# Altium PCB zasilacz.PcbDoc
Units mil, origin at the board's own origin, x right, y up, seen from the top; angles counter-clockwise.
Board outline 7530 x 5310 mil, 2 copper layers (Top Layer, Bottom Layer); 78 components, 40 nets, 194 pads, 25 vias.
Unrouted connection lines stored in the file: 3.
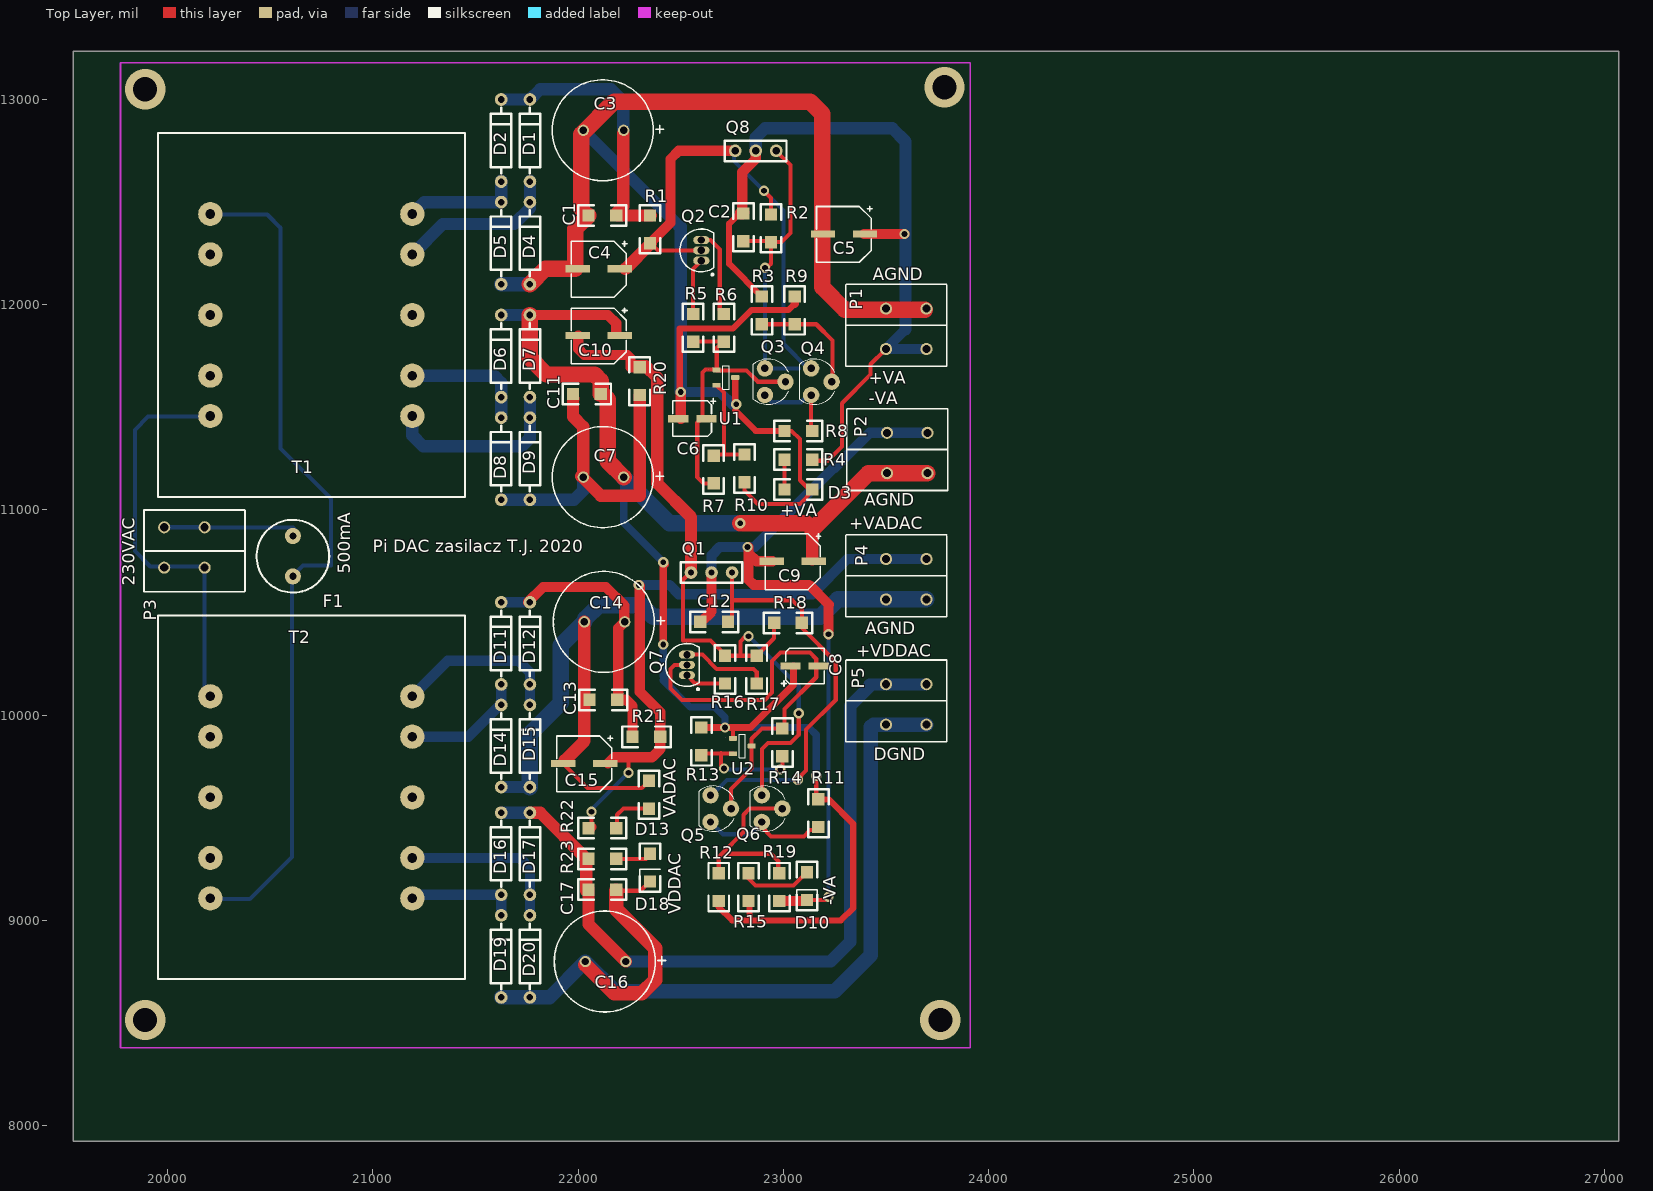
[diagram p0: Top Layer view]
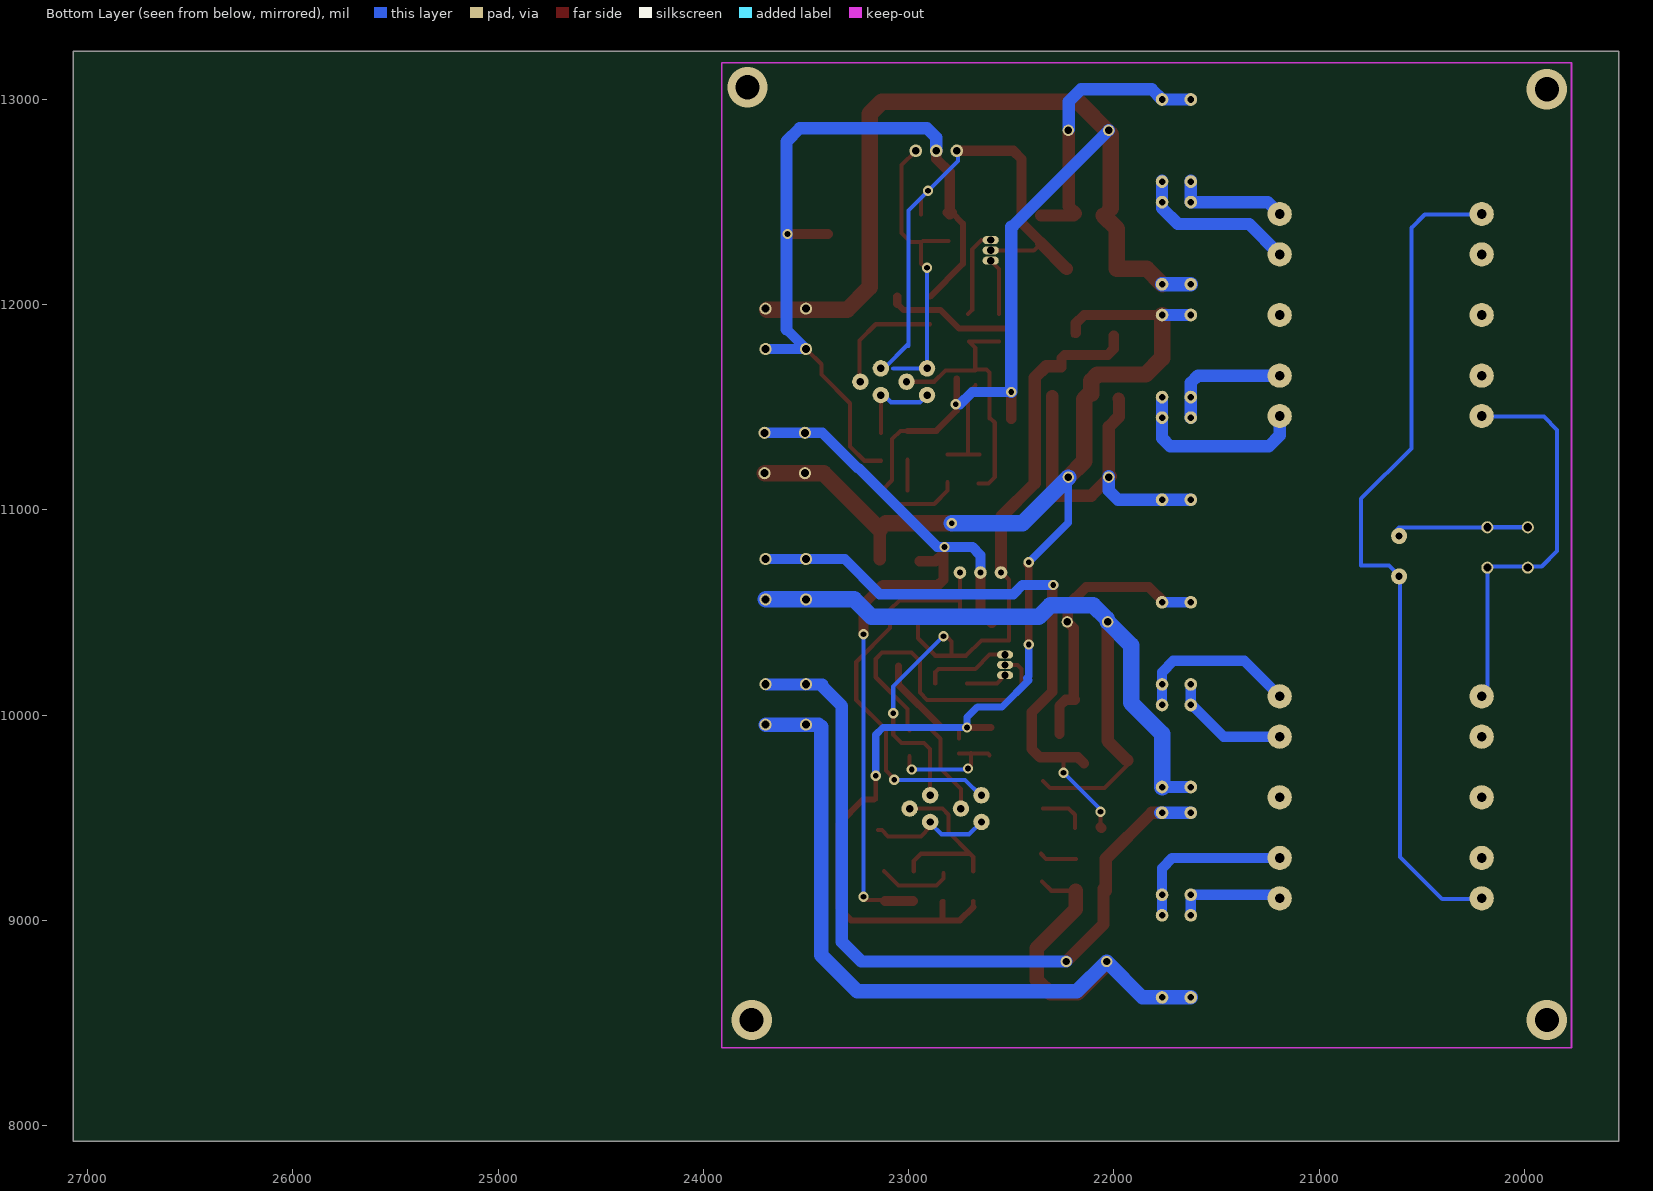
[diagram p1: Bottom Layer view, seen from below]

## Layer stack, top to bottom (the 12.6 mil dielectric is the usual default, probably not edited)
Top Solder: solder mask 0.4, Solder Resist, Dk 3.5
Top Layer: signal copper 1.4
Dielectric 1: dielectric 12.6, FR-4, Dk 4.8
Bottom Layer: signal copper 1.4
Bottom Solder: solder mask 0.4, Solder Resist, Dk 3.5

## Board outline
19540,7925 27070,7925 27070,13235 19540,13235

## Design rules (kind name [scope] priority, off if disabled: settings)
Clearance [All] p1: gap=10
PolygonConnect [All] p1: connectstyle=Relief reliefconductorwidth=10 reliefentries=4 polygonreliefangle="90 Angle" airgapwidth=10
RoomDefinition zasilacz [InComponentClass('zasilacz')] p1: confinementstyle=ConfineIn formatcopy=TRUE lockcomponents=FALSE outline 0,0 2000,0 2000,1000 0,1000
RoutingVias [All] p1: holewidth=28 width=50 viastyle="Through Hole" minholewidth=28 minwidth=50 maxholewidth=28 maxwidth=50
SolderMaskExpansion [All] p1: expansion=4
Width VA- [InNet('VA-')] p1: maxlimit=50 minlimit=50 preferedwidth=50
Width VA+ [InNet('VA+')] p2: maxlimit=50 minlimit=50 preferedwidth=50
Width VDDAC [InNet('+VDDAC')] p3: maxlimit=60 minlimit=60 preferedwidth=60
Width VADAC [InNet('+VADAC')] p4: maxlimit=50 minlimit=50 preferedwidth=50
Width board [All] p5: maxlimit=20 minlimit=20 preferedwidth=20
Width GND [InNet('GND')] p6: maxlimit=60 minlimit=60 preferedwidth=60
Width AGND [InNet('AGND')] p7: maxlimit=50 minlimit=50 preferedwidth=50
30 further rules are at their usual default settings.

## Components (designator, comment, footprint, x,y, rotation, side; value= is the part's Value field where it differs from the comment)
C1 "" 1206 22185,12435 r180 top
C2 "100n" 1206 22805,12445 r270 top
C3 "1000u/35v" 1000u/35v 22025,12850 r0 top
C4 "47u" 47u/25v 22100,12175 r0 top
C5 "47u" 47u/25v 23295,12345 r0 top
C6 "10u" 10uf/25v 22555,11445 r0 top
C7 "1000u/35v" 1000u/35v 22025,11160 r0 top
C8 "10u" 10uf/25v 23105,10240 r180 top
C9 "47u" 47u/25v 23045,10750 r0 top
C10 "47u" 47u/25v 22100,11850 r0 top
C11 "100n" 1206 22110,11565 r180 top
C12 "100n" 1206 22730,10455 r180 top
C13 "" 1206 22190,10075 r180 top
C14 "1000u/35v" 1000u/35v 22030,10455 r0 top
C15 "47u" 47u/25v 22030,9765 r0 top
C16 "1000u/35v" 1000u/35v 22035,8800 r0 top
C17 "" 1206 22050,9150 r0 top
D1 "" DIODE0.4 21765,12600 r90 top
D2 "" DIODE0.4 21625,12600 r90 top
D3 "LED0" 1206 23005,11100 r0 top
D4 "" DIODE0.4 21765,12100 r90 top
D5 "" DIODE0.4 21625,12100 r90 top
D6 "" DIODE0.4 21625,11550 r90 top
D7 "" DIODE0.4 21765,11550 r90 top
D8 "" DIODE0.4 21625,11050 r90 top
D9 "" DIODE0.4 21765,11050 r90 top
D10 "LED0" 1206 23115,9235 r270 top
D11 "" DIODE0.4 21625,10150 r90 top
D12 "" DIODE0.4 21765,10150 r90 top
D13 "LED0" 1206 22345,9545 r90 top
D14 "" DIODE0.4 21625,9650 r90 top
D15 "" DIODE0.4 21765,9650 r90 top
D16 "" DIODE0.4 21625,9125 r90 top
D17 "" DIODE0.4 21765,9125 r90 top
D18 "LED0" 1206 22350,9325 r270 top
D19 "" DIODE0.4 21625,8625 r90 top
D20 "" DIODE0.4 21765,8625 r90 top
F1 "500mA" BEZP_OKR 20610,10775 r270 top
P1 "" wago 23500,11800 r0 top
P2 "" wago 23505,11195 r0 top
P3 "230VAC" wago 20180,10900 r180 top
P4 "" wago 23500,10580 r0 top
P5 "" wago 23500,9970 r0 top
Q1 "BD139" TO-126#1 22750,10695 r0 top
Q2 "BF245" TO-226-AA 22600,12265 r0 top
Q3 "BC547" to-92 22910,11625 r0 top
Q4 "BC547" to-92 23135,11625 r0 top
Q5 "BC557" to-92 22645,9545 r0 top
Q6 "BC557" to-92 22895,9545 r0 top
Q7 "BF245" TO-226-AA 22530,10245 r0 top
Q8 "BD140" TO-126#2 22765,12750 r180 top
R1 "10R" 1206 22350,12300 r90 top
R2 "680R" 1206 22940,12440 r270 top
R3 "820R" 1206 22895,12040 r270 top
R4 "2k2" 1206 23140,11245 r180 top
R5 "1k" 1206 22560,11955 r270 top
R6 "10R" 1206 22710,11955 r270 top
R7 "1k" 1206 22660,11130 r90 top
R8 "680R" 1206 23140,11385 r180 top
R9 "1k" 1206 23055,11905 r90 top
R10 "1k" 1206 22810,11270 r270 top
R11 "680R" 1206 23170,9590 r270 top
R12 "1k" 1206 22685,9095 r90 top
R13 "1k" 1206 22600,9940 r270 top
R14 "1k" 1206 22995,9800 r90 top
R15 "2k2" 1206 22830,9095 r90 top
R16 "1K" 1206 22715,10155 r90 top
R17 "10R" 1206 22870,10155 r90 top
R18 "680R" 1206 23090,10450 r180 top
R19 "820R" 1206 22980,9230 r270 top
R20 "10R" 1206 22300,11695 r270 top
R21 "10R" 1206 22400,9895 r180 top
R22 "1k" 1206 22050,9450 r0 top
R23 "1k" 1206 22050,9300 r0 top
T1 "trafo ZZ2" "TRAFO ZZ7" 20700,11950 r90 top
T2 "trafo ZZ2" "TRAFO ZZ7" 20700,9600 r90 top
U1 "TL431" SOT23-3 22720,11645 r0 top
U2 "TL431" SOT23-3 22800,9850 r0 top

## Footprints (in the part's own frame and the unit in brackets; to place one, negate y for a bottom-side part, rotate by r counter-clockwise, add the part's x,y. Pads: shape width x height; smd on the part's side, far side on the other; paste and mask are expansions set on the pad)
10uf/25v [mm]
  rect 2.5x0.9 smd: 1(1.8,0) 2(-1.7,0)
  silkscreen extent -2.4,-2.2 2.9,2.5
47u/25v [mm]
  rect 3x0.9 smd: 1(2.6,0) 2(-2.6,0)
  silkscreen extent -3.4,-3.5 3.5,3.4
1000u/35v [mm]
  round 1.4 hole 0.9: 1(5,0) 2(0,0)
  silkscreen extent -3.84,-6.25 9.97,6.25
1206 [mil]
  rect 60x60 smd: 1(0,0) 2(135,0)
  silkscreen extent -50,-50 185,50
BEZP_OKR [mm]
  round 2 hole 0.9: 1(-2.5,0) 2(2.5,0)
  silkscreen extent -4.5,-4.5 4.5,4.5
DIODE0.4 [mil]
  round 62 hole 32: 1(0,0) 2(400,0)
  silkscreen extent 40,-50 360,50
SOT23-3 [mm] "SOT23, 3 pin"
  round 0.5 on Mech15: 0(0,0)
  rrect25% 1x0.6 smd: 1(-1.15,0.95) 2(-1.15,-0.95) 3(1.15,0)
  silkscreen extent -0.38,-1.45 0.38,1.45, body extent -1.4,-1.45 1.4,1.45, height 1.29
to-92 [mil]
  round 80 hole 36: 1(0,65) 2(100,0) 3(0,-65)
  silkscreen extent -56,-110 115,110, body extent -55,-95 107,95, height 405
TO-126#1 [mil]
  round 62 hole 28: 1(-200,0) 2(-100,0) 3(0,0)
  silkscreen extent -250,-50 50,50
TO-126#2 [mil]
  round 62 hole 35.43: 1(0,0) 2(-100,0) 3(-200,0)
  silkscreen extent -250,-50 50,50
TO-226-AA [mm] "TO, Flat Index; 3 In-Line, Axial Leads; Body Dia. 4.8mm; Leads 0.55 x 0.51 mm (max)"
  oval 2x1 hole 0.9: 1(0,-1.27) 2(0,0) 3(0,1.27)
  silkscreen extent -2.65,-3.13 1.52,2.65, body extent -2.66,-2.66 1.52,2.66, height 5.33
"TRAFO ZZ7" [mm]
  round 3 hole 1.2: 1(-12.5,12.5) 2(-7.5,12.5) 3(0,12.5) 4(7.5,12.5) 5(12.5,12.5) 6(12.5,-12.5) 7(7.5,-12.5) 8(0,-12.5) 9(-7.5,-12.5) 10(-12.5,-12.5)
  silkscreen extent -22.5,-19 22.5,19
wago [mm]
  round 1.5 hole 1: 1(0,4.6) 1(5,4.6) 2(0,-0.4) 2(5,-0.4)
  silkscreen extent -5,-2.54 7.5,7.6

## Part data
C1 C2 C11 C12 C13 C17: library part Cap, "Capacitor"
C3 C4 C5 C6 C7 C8 C9 C10 C14 C15 C16: library part ELECTRO2, "Electrolytic Capacitor"
D1 D2 D4 D5 D6 D7 D8 D9 D11 D12 D14 D15 D16 D17 D19 D20: library part "Diode 1N4007", "1 Amp General Purpose Rectifier"
D3 D10 D13 D18: "Typical INFRARED GaAs LED"
F1: library part "Fuse 1", "Fuse"
P1 P2 P3 P4 P5: library part "Header 2", "Header, 2-Pin"
Q1 Q3 Q4: library part NPN, "NPN Bipolar Transistor"
Q2 Q7: library part "JFET N"
Q5 Q6 Q8: library part PNP, "PNP Bipolar Transistor"
R1 R2 R3 R4 R5 R6 R7 R8 R9 R10 R11 R12 R13 R14 R15 R16 R17 R18 R19 R20 R21 R22 R23: library part Res2, "Resistor"

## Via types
v1: diameter 50, hole 28, Top Layer to Bottom Layer, 21 vias
v2: diameter 196.85, hole 118.11, Top Layer to Bottom Layer, 4 vias

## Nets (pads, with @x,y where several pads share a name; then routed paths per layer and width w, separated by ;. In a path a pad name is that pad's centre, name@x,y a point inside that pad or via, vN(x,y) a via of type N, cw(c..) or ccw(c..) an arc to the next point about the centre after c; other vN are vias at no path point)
+VADAC: C15.1 P4.1 R21.1 R22.1 | length 3047.8
  Top Layer w20: R22.1@22065,9455 v1(22065,9530) ; v1(22245,9720) 22245,9795
  Top Layer w50: R22.1@22060,9450 R22.1@22065,9455 ; C15.1@22145,9765 22175,9795 22245,9795 22360,9795 22400,9835 R21.1 22400,10015 22300,10115 22300,10630 v1(22295,10635)
  Bottom Layer w20: v1@22055,9530 v1(22245,9720)
  Bottom Layer w50: v1(22295,10635) 22445,10635 22490,10590 23140,10590 23311.1,10761.1 23420,10761.1 P4.1@23700,10761.1
+VDDAC: C16.1 C17.1 D16.2 D17.2 P5.1 R23.1 | length 3797.4
  Top Layer w60: D17.2 21815,9525 22040,9300 C17.1@22040,9145 ; C17.1@22050,9155 C17.1 22050,8981.85 C16.1
  Bottom Layer w60: D16.2 D17.2 D17.2@21775,9525 ; C16.1 23230,8800 23325,8895 23325,10045 23425,10145 ; 23420,10150 P5.1@23690,10150
AGND: C1.2 C3.2 C4.2 C5.2 C6.2 C7.1 C8.1 C9.1 C10.1 C11.1 C13.2 C14.2 C15.2 D3.2 D4.1 D5.1 D6.2 D7.2 D13.2 D14.1 D15.1 P1.1 P2.2 P4.2 R8.2 R9.2 R10.2 R11.1 R12.1 R13.1 R15.1 U1.3 U2.1 | length 19841.6
  Top Layer w20: C15.2@21930,9765 21930,9760 22045,9645 22310,9645 D13.2 ; C10.1@22185,11863.43 C10.1@22198.43,11850 ; R12.1@22685,9065 R12.1 ; U2.1 22754.72,9939.72 22755,9940 ; R10.2 22810,11095 22875,11030 23080,11030 D3.2@23145,11095 ; R15.1 R15.1@22835,9090 ; R8.2 23040,11385 23080,11345 23080,11145 23125,11100 D3.2 D3.2@23145,11100 ; R11.1@23160,9590 v1(23160,9705)
  Top Layer w30: v1@22510,11560 22495,11575 22495,11885 22755,11885 22845,11975 23025,11975 23055,12005 ; R12.1@22685,9065 22750,9000 22835,9000 ; 22765,11485 22865,11385 R8.2 ; v1@22765,11515 U1.3@22765,11640 ; R15.1@22835,9090 22835,9000 ; R11.1 23220,9590 23340,9470 23340,9060 23280,9000 22835,9000
  Top Layer w35: v1(22415,10345) 22415,10725 22425,10735 v1(22415,10745) ; R13.1 v1(22715,9940) 22755,9940 22840,9940 23049.88,10149.88 C8.1@23049.88,10240
  Top Layer w40: 23055,12005 R9.2
  Top Layer w50: D7.2 22145,11950 22185,11910 C10.1@22185,11863.43 ; C6.2@22499.88,11445 v1(22499.88,11574.88)
  Top Layer w60: C15.2@21935,9780 22030,9875 C14.2 ; C1.2@22050,12430 C1.2 ; 23110,10935 23140,10905 C9.1@23140,10760 ; 23414.25,11179.25 23430,11179.25
  Top Layer w70: 22015,12470 C1.2 ; 23298.9,11976.1 23310,11975
  Top Layer w80: D7.2 21765,11740 21845,11660 22080,11660 22110,11630 C11.1 ; D4.1 21840,12175 21985,12175 21985,12370 C1.2 ; 22015,12470 22015,12830 22175,12990 23130,12990 23190,12930 23190,12175 ; C11.1@22120,11565 22145,11540 22145,11236.85 C7.1 ; v1(22790,10935) 23110,10935 ; 23140,10905 23414.25,11179.25 ; 23190,12160 23190,12085 23298.9,11976.1 ; 23310,11975 P1.1@23690,11976.1 ; 23430,11179.25 P2.2@23700,11179.25
  Bottom Layer w20: C7.1@22221.85,11158.15 C7.1 ; 22490,12385 22500,12385 ; v1@22750,11515 v1(22770,11515)
  Bottom Layer w35: C7.1@22221.85,11158.15 22221.85,10938.15 v1(22415,10745) ; v1(22415,10345) 22415,10190 22425,10180 22415,10170 22545,10040 22665,10040 22715,9990 v1(22715,9940) 23125,9940 23160,9905 v1(23160,9705)
  Bottom Layer w50: v1(22499.88,11574.88) 22690.12,11574.88 v1@22750,11515
  Bottom Layer w60: D14.1 D15.1 ; D6.2 D7.2 ; C3.2 22490,12385 ; C7.1@22220,11160 C7.1@22221.85,11158.15 ; v1(22499.88,11574.88) 22499.88,12380.12
  Bottom Layer w70: D5.1 D4.1
  Bottom Layer w80: D15.1 21765,9910 21915,10060 21915,10340 C14.2 ; C14.2@22035,10470 22100,10535 22310,10535 22365,10480 23180.9,10480 23265.16,10564.25 23420,10564.25 P4.2@23695,10564.25 ; C7.1@22221.85,11158.15 22445,10935 v1(22790,10935)
GND: C16.2 C17.2 D18.2 D19.1 D20.1 P5.2 | length 4510.9
  Top Layer w20: C17.2@22180,9145 22185,9145 22305,9145 D18.2
  Top Layer w70: C16.2@22035,8785 22175,8645 22310,8645 22375,8710 22375,8865 22185,9055 C17.2@22185,9145
  Bottom Layer w20: 23425,9944.25 23425,9945 ; 23435,9950 23439.25,9954.25
  Bottom Layer w70: D19.1 D20.1 21860,8625 C16.2 22180,8655 23250,8655 23425,8830 23425,9944.25 ; 23439.25,9954.25 23500,9954.25 P5.2@23696.85,9954.25
NetC1_1: C1.1 C3.1 D1.2 D2.2 R1.2 | length 1354.2
  Top Layer w60: C3.1@22220,12835 22220,12480 22185,12445 22195,12435 R1.2 R1.2@22355,12435
  Bottom Layer w60: D2.2 D1.2 21815,13050 22160,13050 22220,12990 C3.1@22220,12855
NetC2_2: C2.2 Q3.1 Q8.3 R2.2 | length 1460.9
  Top Layer w20: C2.2 R2.2@22930,12310 ; v1(22910,12180) 22920,12180 22940,12200 R2.2@22940,12300 ; R2.2 22990,12305 23035,12350 23035,12680 Q8.3
  Bottom Layer w20: v1(22910,12180) Q3.1 23075,11690
NetC4_1: C4.1 Q2.2 Q4.1 Q8.1 R1.1 R2.1 | length 2573.7
  Top Layer w20: R1.1@22355,12300 22390,12265 Q2.2 ; v1(22905,12555) 22940,12520 R2.1
  Top Layer w50: R1.1@22355,12305 22450,12400 22450,12710 22490,12750 Q8.1
  Top Layer w60: C4.1@22230,12175 R1.1@22355,12300
  Bottom Layer w20: Q8.1@22760,12755 22760,12700 v1(22905,12555) 23000,12460 23000,11800 ; 23005,11805 23120,11690 Q4.1
NetC6_1: C6.1 Q3.2 R5.2 R6.2 R7.1 U1.1 | length 1332.1
  Top Layer w20: R5.2 22705,11820 22675,11790 22675,11685 22620,11685 22605,11670 C6.1@22605,11445 ; C6.1@22600,11445 22580,11425 22580,11160 22610,11130 R7.1 ; U1.1@22675,11680 22820,11680 22875,11625 Q3.2@23005,11625
NetC7_2: C7.2 C11.2 D8.1 D9.1 R20.2 | length 1702.2
  Top Layer w60: C11.2@21977.5,11542.5 21975,11540 21975,11455 22025,11405 C7.2 ; C7.2@22015,11165 22110,11070 22300,11070 R20.2@22300,11555
  Bottom Layer w60: D8.1 D9.1 21980,11050 22025,11095 C7.2 C7.2@22025,11165
NetC8_2: C8.2 Q5.2 Q7.2 R14.2 U2.3 | length 2065
  Top Layer w20: Q7.2@22525,10245 22470,10245 22450,10225 22450,10130 22505,10075 22910,10075 22945,10110 22945,10265 22985,10305 23130,10305 23160.12,10274.88 23160.12,10185.12 23005,10030 23005,9935 R14.2@22995,9925 ; Q5.2 22745,9640 22845,9740 U2.3@22845,9850 ; U2.3 22845.28,9885.28 22895,9935 R14.2@22980,9935
NetC10_2: C10.2 Q1.1 Q6.1 R16.2 R17.2 R18.2 R20.1 | length 3618.9
  Top Layer w20: Q1.1@22545,10695 22510,10660 22510,10365 22645,10365 22720,10290 R17.2 ; 22650,10695 22665,10680 ; 22790,10295 22790,10360 22815,10385 v1(22830,10385) ; R17.2@22875,10295 22955,10375 R18.2 ; Q6.1 22895,9835 22925,9865 23035,9865 23075,9905 v1(23075,10010)
  Top Layer w50: C10.2@22000,11848.43 22000,11785 22030,11755 ; 22035,11755 22240,11755 22255,11740 22255,11695
  Top Layer w60: 22260,11700 22330,11700 22385,11645 22385,11130 22550,10965 Q1.1
  Bottom Layer w20: v1(22830,10385) 23075,10140 v1(23075,10010)
NetC12_1: C12.1 Q1.3 Q5.1 R18.1 | length 2035.9
  Top Layer w20: C12.1 22735,10455 22750,10470 22750,10560 ; Q1.3 22750,10560 ; v1(23070,9685) 23070,9690 23110,9730 23110,9930 23255,10075 23255,10260 23090,10425 R18.1 23090,10515 23045,10560 22750,10560
  Bottom Layer w20: Q5.1@22650,9610 22725,9685 v1(23070,9685)
NetC13_1: C13.1 C14.1 D11.2 D12.2 R21.2 | length 1354
  Top Layer w50: D12.2@21755,10550 21830,10625 22135,10625 22225,10535 C14.1@22225,10460 ; C13.1 22235,10075 22265,10045 R21.2@22265,9910 ; C13.1@22195,10080 22195,10423.15 C14.1
  Bottom Layer w50: D11.2 D12.2@21755,10550
NetD1_1: D1.1 D4.2 T1.7 | length 801
  Bottom Layer w60: T1.7 21340,12393.15 21688.15,12393.15 21765,12470 D4.2 D1.1 D1.1@21765,12605
NetD2_1: D2.1 D5.2 T1.6 | length 564.9
  Bottom Layer w60: T1.6@21190,12440 T1.6 21250,12500 D5.2 D2.1 D2.1@21625,12605
NetD3_1: D3.1 R4.2 | length 150
  Top Layer w20: D3.1@23005,11095 D3.1 R4.2
NetD6_1: D6.1 D8.2 T1.9 | length 617.3
  Bottom Layer w60: T1.9 21590.28,11654.72 21625,11620 D6.1 D8.2
NetD7_1: D7.1 D9.2 T1.10 | length 906.3
  Bottom Layer w60: T1.10 21192.13,11362.87 21245,11310 21725,11310 21765,11350 D9.2 D7.1
NetD10_1: D10.1 R15.2 | length 358.5
  Top Layer w20: R15.2 22830,9205 22865,9170 23050,9170 D10.1@23120,9240
NetD11_1: D11.1 D14.2 T2.7 | length 591.1
  Bottom Layer w20: D14.2@21625,10065 D14.2@21630,10060
  Bottom Layer w50: T2.7 21465.28,9895.28 D14.2@21625,10055 ; D14.2@21625,10065 D11.1
NetD12_1: D12.1 D15.2 T2.6 | length 829.3
  Bottom Layer w20: D15.2@21760,10050 D15.2@21765,10055
  Bottom Layer w50: T2.6 21365,10265 21710,10265 21765,10210 D15.2@21765,10055
NetD13_1: D13.1 R22.2 | length 232.4
  Top Layer w20: R22.2@22190,9450 22190,9515 22220,9545 D13.1
NetD16_1: D16.1 D19.2 T2.10 | length 530
  Bottom Layer w50: T2.10@21195,9125 D16.1 D19.2
NetD17_1: D17.1 D20.2 T2.9 | length 818.5
  Bottom Layer w50: T2.9 21715.28,9304.72 21765,9255 D17.1@21765,9130 ; D20.2 D17.1
NetD18_1: D18.1 R23.2 | length 180.4
  Top Layer w20: R23.2 22330,9300 D18.1@22355,9325
NetF1_1: F1.1 P3.2 | length 641.3
  Bottom Layer w20: P3.2@19983.15,10915.75 20165.75,10915.75 20166.5,10915 20610,10915 F1.1@20620,10905
NetF1_2: F1.2 T1.5 T2.1 | length 4194.7
  Bottom Layer w20: T2.1@20210,9105 20400,9105 20605,9310 F1.2@20605,10696.57 ; T1.5@20210,12445 20215,12440 20485,12440 20550,12375 20550,11300 20795,11055 20795,10730 20660,10730 F1.2@20605,10675
NetP3_1: P3.1 T1.1 T2.5 | length 1974.8
  Bottom Layer w20: T2.5@20205,10110 20180,10135 20180,10718.9 20173.9,10725 19915,10725 19840,10800 19840,11390 19905,11455 T1.1@20205,11455
NetQ2_1: Q2.1 R5.1 | length 276.6
  Top Layer w20: R5.1 22560,12175 Q2.1
NetQ2_3: Q2.3 R6.1 | length 431.9
  Top Layer w20: Q2.3 22645,12315 22690,12270 22690,11975 R6.1
NetQ3_3: Q3.3 Q4.3 R8.1 | length 436.9
  Top Layer w20: R8.1@23135,11375 Q4.3
  Bottom Layer w20: Q3.3 22945,11525 23085,11525 23115,11555 Q4.3@23135,11555
NetQ4_2: Q4.2 R3.2 R9.1 | length 573.1
  Top Layer w20: R3.2 R9.1 23160,11905 23240,11825 Q4.2@23240,11630
NetQ5_3: Q5.3 Q6.3 R11.2 | length 596.6
  Top Layer w20: Q6.3@22895,9475 22895,9455 22940,9410 23100,9410 23130,9440 R11.2@23150,9440
  Bottom Layer w20: Q5.3 22705,9420 22840,9420 Q6.3@22890,9470
NetQ6_2: Q6.2 R12.2 R19.1 | length 866.6
  Top Layer w20: R12.2@22685,9240 22685,9310 22700,9325 ; R19.1@22975,9240 22975,9290 22940,9325 22700,9325 ; Q6.2 22835,9545 22805,9515 22805,9430 22700,9325
NetQ7_1: Q7.1 R16.1 | length 201.6
  Top Layer w20: Q7.1 22570,10155 R16.1
NetQ7_3: Q7.3 R17.1 | length 430.2
  Top Layer w20: Q7.3 22605,10295 22675,10225 22855,10225 22870,10210 R17.1
NetR7_2: R7.2 R10.1 U1.2 | length 507.2
  Top Layer w20: R7.2@22655,11270 R10.1 ; U1.2 22710,11572.32 22710,11270
NetR13_2: R13.2 R14.1 U2.2 | length 561.2
  Top Layer w20: R13.2@22605,9805 22612.6,9812.6 22695,9812.6 ; 22695,9815 22695,9812.6 ; v1(22710,9740) 22695,9755 22695,9812.6 ; U2.2 22695,9812.6 ; v1@22995,9750 R14.1
  Bottom Layer w20: v1(22710,9740) 22715,9735 v1(22985,9735)
VA+: C2.1 C5.1 P1.2 Q8.2 R3.1 R4.1 | length 3876.6
  Top Layer w20: R4.1@23135,11240 23215,11240 23285,11310 23285,11520 23425,11660 23425,11710 P1.2@23495,11780
  Top Layer w30: C2.1@22790,12450 22735,12395 22735,12200 R3.1
  Top Layer w50: C2.1@22790,12450 C2.1@22800,12450 ; C2.1@22800,12440 C2.1@22800,12445 ; C2.1@22810,12450 C2.1@22800,12450 ; Q8.2@22860,12750 22865,12745 22865,12710 22800,12645 C2.1@22800,12450 ; C5.1@23393.43,12345 v1(23590,12345)
  Bottom Layer w50: 22865,12815 22870,12815 ; 23595,11880 23500,11785 23500,11784.25 23694.25,11784.25 P1.2@23695,11785
  Bottom Layer w60: Q8.2 22865,12815 22910,12860 23530,12860 23595,12795 23595,11880
VA-: C9.2 C12.2 D10.2 P2.1 Q1.2 R19.2 | length 4060.4
  Top Layer w20: D10.2 23205,9100 v1(23220,9115)
  Top Layer w50: C12.2@22595,10450 22650,10505 Q1.2 ; v1@22830,10820 22830,10790 ; C9.2@22946.57,10750 22870,10750 22830,10790 ; R19.2 D10.2@23115,9095 ; v1(23220,10395) 23220,10536.06 23221.97,10538.03 23125,10635 22855,10635 22830,10660 22830,10790
  Bottom Layer w20: v1(23220,9115) v1(23220,10395)
  Bottom Layer w50: Q1.2 22650,10780 22690,10820 v1(22825,10820) 22860,10820 23245,11205 23250,11205 23421.1,11376.1 P2.1@23705,11376.1
pads on no net: T1.2 T1.3 T1.4 T1.8 T2.2 T2.3 T2.4 T2.8 U1.0 U2.0
copper on no net:
  other v2: 19890,8515 23765,8515 19890,13050 23785,13060

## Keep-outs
Keep-Out Layer:
  lines w7.87: 19770,8380 19770,13180 23910,13180 23910,8380 19770,8380

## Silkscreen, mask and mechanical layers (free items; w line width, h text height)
Top Overlay:
  lines w7.87: 22225,8715 22230,8720 ; 22300,9175 22300,9225 22300,9250 22400,9250 ; 23065,9130 23065,9150 23165,9150 23165,9130
  text "AGND" at 23435,12120 h60
  text "+VA" at 23415,11615 h60
  text "-VA" at 23415,11515 h60
  text "AGND" at 23395,11020 h60
  text "+VA" at 22985,10970 h60
  text "+VADAC" at 23320,10905 h60
  text "Pi DAC zasilacz T.J. 2020" at 21000,10795 h60
  text "230VAC" at 19840,10630 h60 r90
  text "AGND" at 23400,10395 h60
  text "+VDDAC" at 23355,10285 h60
  text "DGND" at 23440,9780 h60
  text "VADAC" at 22475,9500 h60 r90
  text "-VA" at 23255,9075 h60 r90
  text "VDDAC" at 22500,9030 h60 r90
